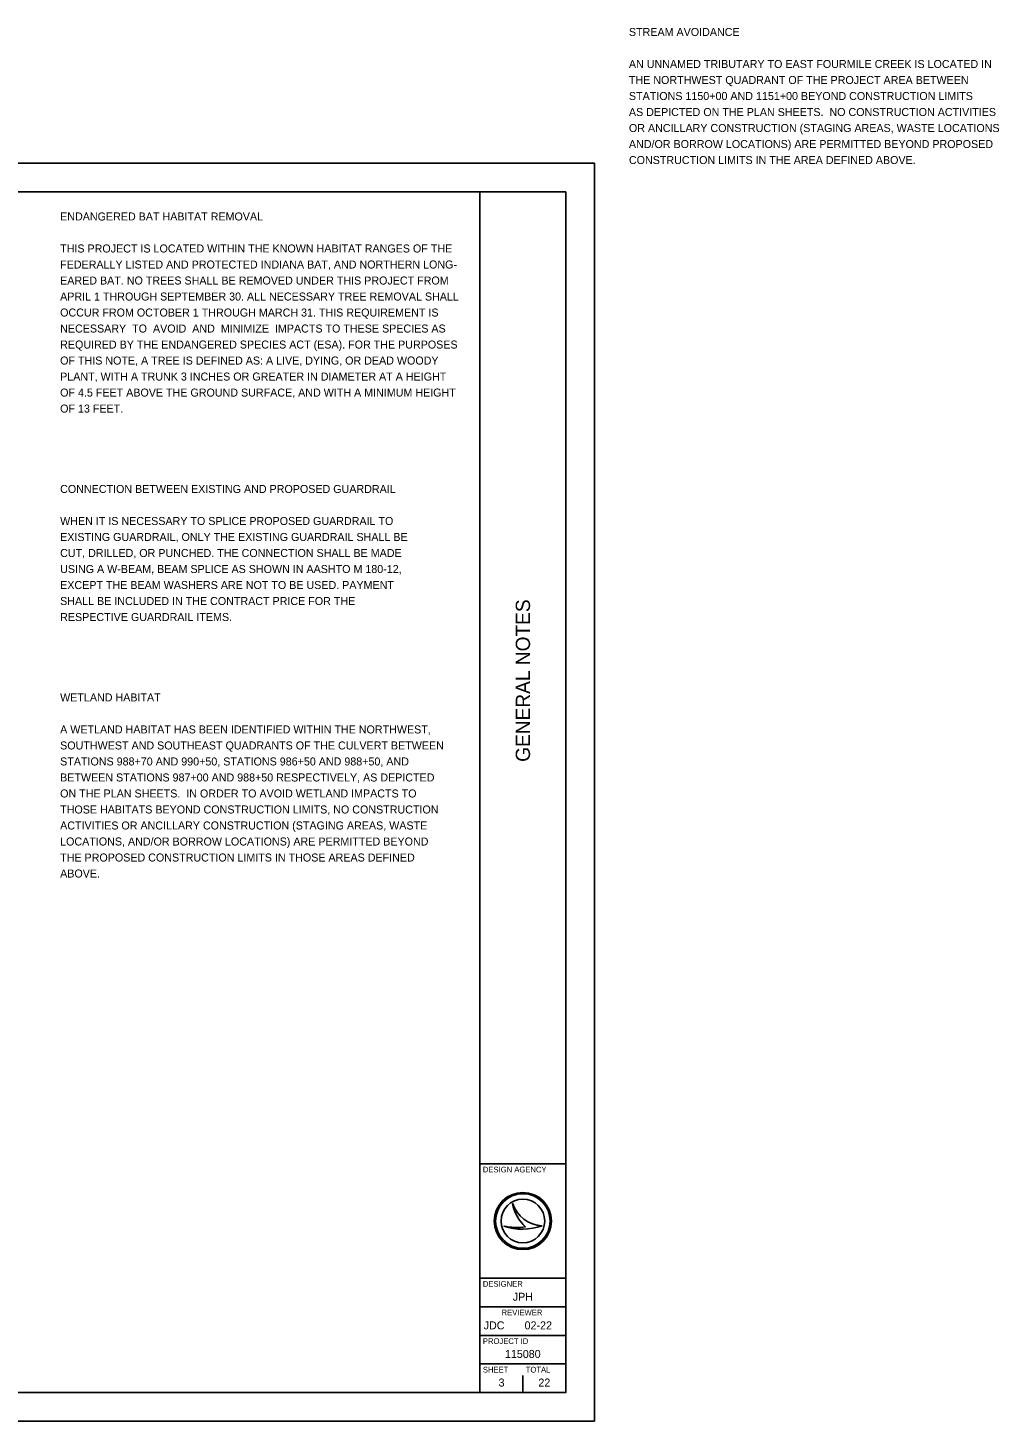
# Model space of a CAD drawing. Extents: x 0 to 41.1, y 0 to 24.4.
# Drawn here: x 24.1 to 41.08, y 0 to 24.37 of the extents above; entities that cross this region are included whole.
import ezdxf

# ---------------------------------------------------------------- set-up
doc = ezdxf.new("R2010")
doc.units = 0
for name, color, linetype in [('SH_Border', 7, 'Continuous'), ('SH_Cut_Line', 7, 'Continuous'), ('SH_Data', 7, 'Continuous'), ('SH_Text', 7, 'Continuous')]:
    doc.layers.add(name, color=color, linetype=linetype)

msp = doc.modelspace()

# ---------------------------------------------------------------- linework, layer by layer
at = {"layer": 'SH_Border'}
for p, q in [((32, 0.5), (32, 21.5)), ((32, 4.5), (33.5, 4.5)), ((32, 2.5), (33.5, 2.5)), ((32, 2), (33.5, 2)), ((32, 1.5), (33.5, 1.5)), ((32, 1), (33.5, 1))]:
    msp.add_line(p, q, dxfattribs=at)
msp.add_lwpolyline([(1.5, 21.5), (33.5, 21.5), (33.5, 0.5), (1.5, 0.5)], close=True, dxfattribs=at)
at = {"layer": 'SH_Cut_Line'}
msp.add_lwpolyline([(0, 0), (34, 0), (34, 22), (0, 22)], close=True, dxfattribs=at)
at = {"layer": 'SH_Data'}
for p, q in [((32.567, 3.81), (32.567, 3.81)), ((32.75, 3.5), (32.75, 3.5)), ((33.087, 3.419), (33.087, 3.419)), ((32.417, 3.41), (32.417, 3.41)), ((32.75, 0.5), (32.75, 0.8)), ((32.375, 0.675), (32.375, 0.675))]:
    msp.add_line(p, q, dxfattribs=at)
for radius in [0.5, 0.477, 0.477, 0.382]:
    msp.add_circle((32.75, 3.5), radius, dxfattribs=at)
for centre, radius, start, end in [((33.116, 3.998), 0.58, 198.9257, 198.9319), ((33.347, 3.97), 0.796, 191.6379, 191.6421), ((33.116, 3.998), 0.58, 198.9319, 267.1657), ((33.347, 3.97), 0.796, 191.6421, 226.0947), ((32.739, 4.37), 1.013, 251.4576, 290.0832), ((32.648, 4.654), 1.266, 259.4964, 259.4995), ((32.739, 4.37), 1.013, 251.4527, 251.4576), ((32.648, 4.654), 1.266, 259.4995, 276.6672)]:
    msp.add_arc(centre, radius, start, end, dxfattribs=at)

# ---------------------------------------------------------------- texts
msp.add_text('GENERAL NOTES', height=0.25, rotation=90, dxfattribs=at).set_placement((32.875, 11.531))
for s, height, p in [('DESIGN AGENCY', 0.1, (32.05, 4.35)), ('DESIGNER', 0.1, (32.05, 2.35)), ('JPH', 0.14, (32.573, 2.105)), ('REVIEWER', 0.1, (32.378, 1.85)), ('JDC', 0.14, (32.064, 1.605)), ('02-22', 0.14, (32.78, 1.605)), ('PROJECT ID', 0.1, (32.05, 1.35)), ('115080', 0.14, (32.436, 1.105)), ('SHEET', 0.1, (32.05, 0.85)), ('3', 0.14, (32.325, 0.605)), ('TOTAL', 0.1, (32.8, 0.85)), ('22', 0.14, (33.021, 0.605))]:
    msp.add_text(s, height=height, dxfattribs=at).set_placement(p)
at = {"layer": 'SH_Text'}
for s, p in [('STREAM AVOIDANCE', (34.604, 24.227)), ('AN UNNAMED TRIBUTARY TO EAST FOURMILE CREEK IS LOCATED IN', (34.604, 23.667)), ('THE NORTHWEST QUADRANT OF THE PROJECT AREA BETWEEN', (34.604, 23.387)), ('STATIONS 1150+00 AND 1151+00 BEYOND CONSTRUCTION LIMITS', (34.604, 23.107)), ('AS DEPICTED ON THE PLAN SHEETS.  NO CONSTRUCTION ACTIVITIES', (34.604, 22.827)), ('OR ANCILLARY CONSTRUCTION (STAGING AREAS, WASTE LOCATIONS', (34.604, 22.547)), ('AND/OR BORROW LOCATIONS) ARE PERMITTED BEYOND PROPOSED', (34.604, 22.267)), ('CONSTRUCTION LIMITS IN THE AREA DEFINED ABOVE.', (34.604, 21.987)), ('ENDANGERED BAT HABITAT REMOVAL', (24.66, 21)), ('THIS PROJECT IS LOCATED WITHIN THE KNOWN HABITAT RANGES OF THE', (24.66, 20.44)), ('FEDERALLY LISTED AND PROTECTED INDIANA BAT, AND NORTHERN LONG-', (24.66, 20.16)), ('EARED BAT. NO TREES SHALL BE REMOVED UNDER THIS PROJECT FROM', (24.66, 19.88)), ('APRIL 1 THROUGH SEPTEMBER 30. ALL NECESSARY TREE REMOVAL SHALL', (24.66, 19.6)), ('OCCUR FROM OCTOBER 1 THROUGH MARCH 31. THIS REQUIREMENT IS', (24.66, 19.32)), ('NECESSARY  TO  AVOID  AND  MINIMIZE  IMPACTS TO THESE SPECIES AS', (24.66, 19.04)), ('REQUIRED BY THE ENDANGERED SPECIES ACT (ESA). FOR THE PURPOSES', (24.66, 18.76)), ('OF THIS NOTE, A TREE IS DEFINED AS: A LIVE, DYING, OR DEAD WOODY', (24.66, 18.48)), ('PLANT, WITH A TRUNK 3 INCHES OR GREATER IN DIAMETER AT A HEIGHT', (24.66, 18.2)), ('OF 4.5 FEET ABOVE THE GROUND SURFACE, AND WITH A MINIMUM HEIGHT', (24.66, 17.92)), ('OF 13 FEET.', (24.66, 17.64)), ('CONNECTION BETWEEN EXISTING AND PROPOSED GUARDRAIL', (24.66, 16.234)), ('WHEN IT IS NECESSARY TO SPLICE PROPOSED GUARDRAIL TO', (24.66, 15.674)), ('EXISTING GUARDRAIL, ONLY THE EXISTING GUARDRAIL SHALL BE', (24.66, 15.394)), ('CUT, DRILLED, OR PUNCHED. THE CONNECTION SHALL BE MADE', (24.66, 15.114)), ('USING A W-BEAM, BEAM SPLICE AS SHOWN IN AASHTO M 180-12,', (24.66, 14.834)), ('EXCEPT THE BEAM WASHERS ARE NOT TO BE USED. PAYMENT', (24.66, 14.554)), ('SHALL BE INCLUDED IN THE CONTRACT PRICE FOR THE', (24.66, 14.274)), ('RESPECTIVE GUARDRAIL ITEMS.', (24.66, 13.994)), ('WETLAND HABITAT', (24.66, 12.588)), ('A WETLAND HABITAT HAS BEEN IDENTIFIED WITHIN THE NORTHWEST,', (24.66, 12.028)), ('SOUTHWEST AND SOUTHEAST QUADRANTS OF THE CULVERT BETWEEN', (24.66, 11.748)), ('STATIONS 988+70 AND 990+50, STATIONS 986+50 AND 988+50, AND', (24.66, 11.468)), ('BETWEEN STATIONS 987+00 AND 988+50 RESPECTIVELY, AS DEPICTED', (24.66, 11.188)), ('ON THE PLAN SHEETS.  IN ORDER TO AVOID WETLAND IMPACTS TO', (24.66, 10.908)), ('THOSE HABITATS BEYOND CONSTRUCTION LIMITS, NO CONSTRUCTION', (24.66, 10.628)), ('ACTIVITIES OR ANCILLARY CONSTRUCTION (STAGING AREAS, WASTE', (24.66, 10.348)), ('LOCATIONS, AND/OR BORROW LOCATIONS) ARE PERMITTED BEYOND', (24.66, 10.068)), ('THE PROPOSED CONSTRUCTION LIMITS IN THOSE AREAS DEFINED', (24.66, 9.788)), ('ABOVE.', (24.66, 9.508))]:
    msp.add_text(s, height=0.14, dxfattribs=at).set_placement(p)

doc.saveas('drawing.dxf')
